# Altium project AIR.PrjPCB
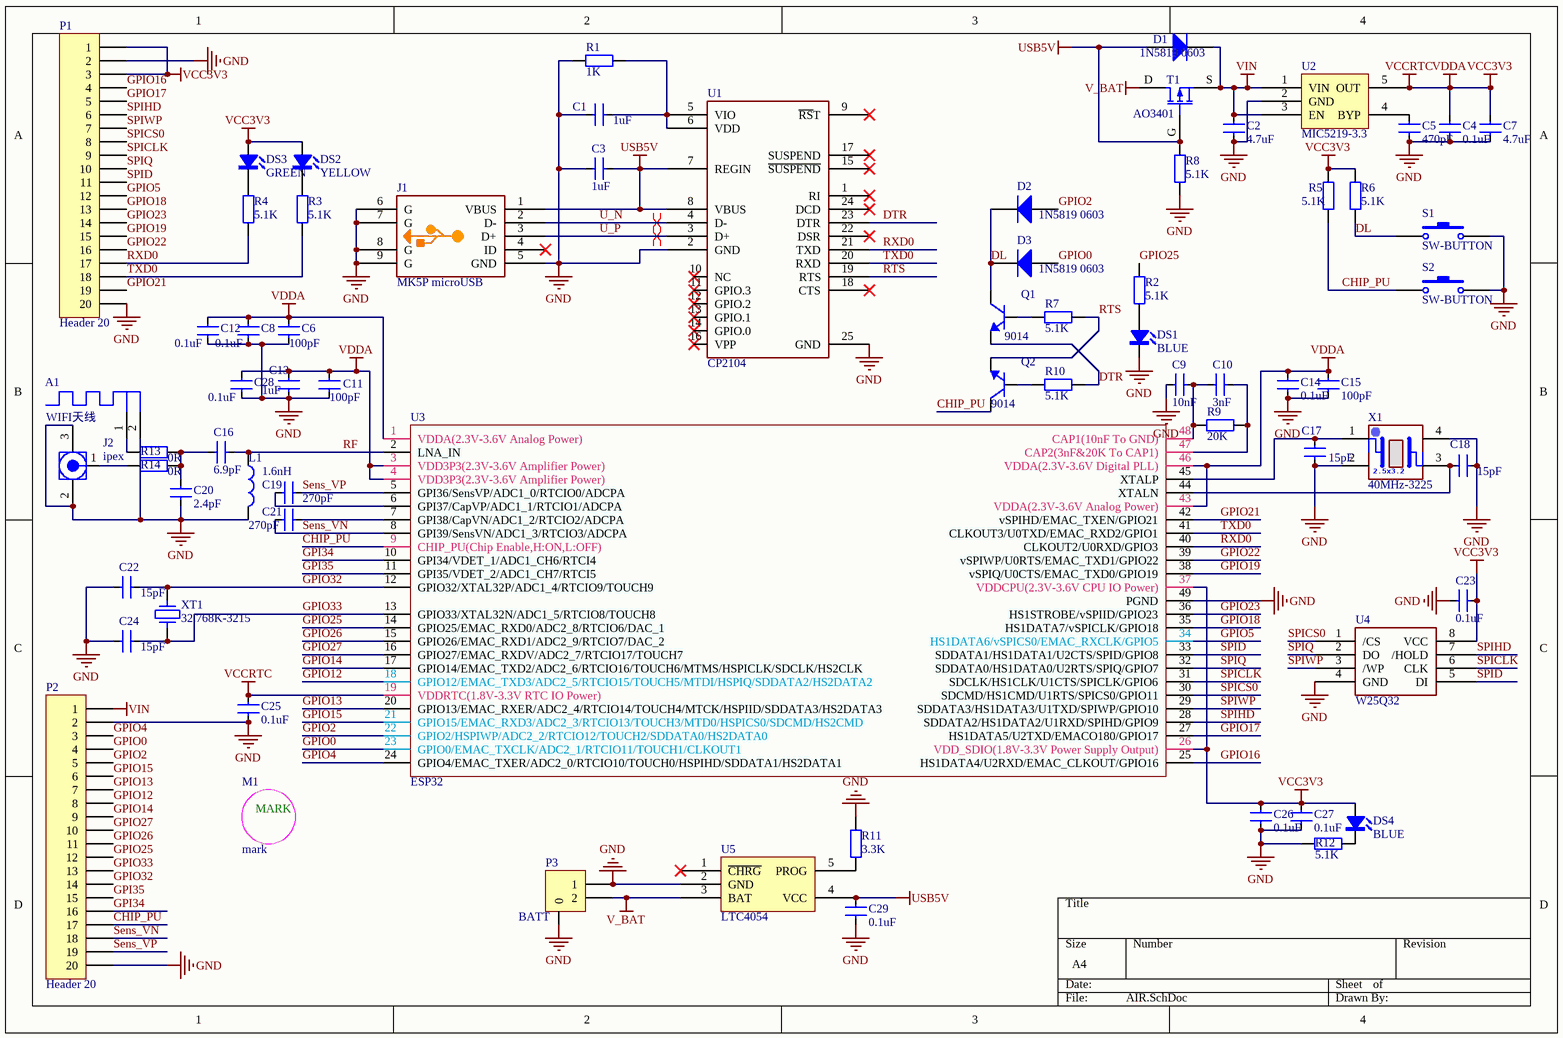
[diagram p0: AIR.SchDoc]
1 sheet, 70 parts. Net scope: global (net labels, ports and power ports of the same name join across sheets).
Board file: AIR.PcbDoc

## Sheet AIR.SchDoc
size A4

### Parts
A1  WIFI天线  [2.4G]
C1  1uF  [C0402]
C2  4.7uF  [C0603]
C3  1uF  [C0402]
C4  0.1uF  [C0402]
C5  470pF  [C0402]
C6  100pF  [C0402]
C7  4.7uF  [C0603]
C8  0.1uF  [C0402]
C9  10nF  [C0402]
C10  3nF  [C0402]
C11  100pF  [C0402]
C12  0.1uF  [C0402]
C13  1uF  [C0402]
C14  0.1uF  [C0402]
C15  100pF  [C0402]
C16  6.9pF  [C0402]
C17  15pF  [C0402]
C18  15pF  [C0402]
C19  270pF  [C0402]
C20  2.4pF  [C0402]
C21  270pF  [C0402]
C22  15pF  [C0402]
C23  0.1uF  [C0402]
C24  15pF  [C0402]
C25  0.1uF  [C0402]
C26  0.1uF  [C0402]
C27  0.1uF  [C0402]
C28  0.1uF  [C0402]
C29  0.1uF  [C0402]
D1  1N5819 0603  [SOD523]
D2  1N5819 0603  [SOD523]
D3  1N5819 0603  [SOD523]
DS1  BLUE  [LED0402]
DS2  YELLOW  [LED0402]
DS3  GREEN  [LED0402]
DS4  BLUE  [LED0402]
J1  MK5P microUSB  [MICROUSB]
J2  ipex  [I-PEX SOCKET]
L1  1.6nH  [L0402]
M1  mark  [ZY_UR-3X2]
P1  Header 20  [HDR1X20-M]
P2  Header 20  [HDR1X20-M]
P3  BATT  [PH1.25-T]
Q1  9014  [SOT23]
Q2  9014  [SOT23]
R1  1K  [R0402]
R2  5.1K  [R0402]
R3  5.1K  [R0402]
R4  5.1K  [R0402]
R5  5.1K  [R0402]
R6  5.1K  [R0402]
R7  5.1K  [R0402]
R8  5.1K  [R0402]
R9  20K  [R0402]
R10  5.1K  [R0402]
R11  3.3K  [R0402]
R12  5.1K  [R0402]
R13  0R  [R0402]
R14  0R  [R0402]
S1  SW-BUTTON  [MINIBUTTON]
S2  SW-BUTTON  [MINIBUTTON]
T1  AO3401  [SOT23]
U1  CP2104  [QFN24]
U2  MIC5219-3.3  [SOT23-5]
U3  ESP32  [QFN40P600X600X100-48N]
U4  W25Q32  [WSON-SPIFLASH]
U5  LTC4054  [SOT23-5]
X1  40MHz-3225  [XTAL3225]
XT1  32.768K-3215  [Y3215]

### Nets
GND: A1.2(G) C1.2 C2.1 C3.1 C4.1 C5.2 C6.1 C7.1 C8.1 C9.2 C11.1 C12.1 C13.1 C14.1 C15.1 C17.2 C18.2 C20.1 C22.1 C23.2 C24.1 C25.1 C26.1 C27.1 C28.1 C29.1 DS1.K J1.5(GND) J1.6(G) J1.7(G) J1.8(G) J1.9(G) J2.2(GND) J2.3(GND) L1.1 P1.2 P1.20 P2.2 P2.20 P3.0 P3.1 R1.1 R8.1 R11.2 R12.2 S1.2 S2.2 U1.2(GND) U1.25(GND) U2.2(GND) U3.49(PGND) U4.4(GND) U5.2(GND) X1.2(NC1) X1.4(NC2)
USB5V: C3.2 C29.2 D1.A J1.1(VBUS) R8.2 T1.G U1.7(REGIN) U1.8(VBUS) U5.4(VCC)
V_BAT: P3.2 T1.D U5.3(BAT)
VCC3V3: C4.2 C6.2 C7.2 C8.2 C11.2 C12.2 C13.2 C14.2 C15.2 C23.1 C25.2 C26.2 C27.2 C28.2 DS2.A DS3.A DS4.A P1.1 P1.3 R5.1 R6.2 U2.5(OUT) U3.1(VDDA(2.3V-3.6V_Analog_Power)) U3.3(VDD3P3(2.3V-3.6V_Amplifier_Power)) U3.4(VDD3P3(2.3V-3.6V_Amplifier_Power)) U3.19(VDDRTC(1.8V-3.3V_RTC_IO_Power)) U3.26(VDD_SDIO(1.8V-3.3V_Power_Supply_Output)) U3.37(VDDCPU(2.3V-3.6V_CPU_IO_Power)) U3.43(VDDA(2.3V-3.6V_Analog_Power)) U3.46(VDDA(2.3V-3.6V_Digital_PLL)) U4.8(VCC)  [also labelled VCCRTC, VDDA]
VIN: C2.2 D1.K P2.1 T1.S U2.1(VIN) U2.3(EN)
CHIP_PU: P2.17 Q2.C R5.2 S2.1 U3.9(CHIP_PU(Chip_Enable,H:ON,L:OFF))
DL: D2.K D3.K Q1.C R6.1 S1.1
DTR: Q1.E R10.1 U1.23(DTR)
GPI34: P2.16 U3.10(GPI34/VDET_1/ADC1_CH6/RTCI4)
GPI35: P2.15 U3.11(GPI35/VDET_2/ADC1_CH7/RTCI5)
GPIO0: D3.A P2.4 U3.23(GPIO0/EMAC_TXCLK/ADC2_1/RTCIO11/TOUCH1/CLKOUT1)
GPIO2: D2.A P2.5 U3.22(GPIO2/HSPIWP/ADC2_2/RTCIO12/TOUCH2/SDDATA0/HS2DATA0)
GPIO4: P2.3 U3.24(GPIO4/EMAC_TXER/ADC2_0/RTCIO10/TOUCH0/HSPIHD/SDDATA1/HS2DATA1)
GPIO5: P1.12 U3.34(HS1DATA6/vSPICS0/EMAC_RXCLK/GPIO5)
GPIO12: P2.8 U3.18(GPIO12/EMAC_TXD3/ADC2_5/RTCIO15/TOUCH5/MTDI/HSPIQ/SDDATA2/HS2DATA2)
GPIO13: P2.7 U3.20(GPIO13/EMAC_RXER/ADC2_4/RTCIO14/TOUCH4/MTCK/HSPIID/SDDATA3/HS2DATA3)
GPIO14: P2.9 U3.17(GPIO14/EMAC_TXD2/ADC2_6/RTCIO16/TOUCH6/MTMS/HSPICLK/SDCLK/HS2CLK)
GPIO15: P2.6 U3.21(GPIO15/EMAC_RXD3/ADC2_3/RTCIO13/TOUCH3/MTD0/HSPICS0/SDCMD/HS2CMD)
GPIO16: P1.4 U3.25(HS1DATA4/U2RXD/EMAC_CLKOUT/GPIO16)
GPIO17: P1.5 U3.27(HS1DATA5/U2TXD/EMACO180/GPIO17)
GPIO18: P1.13 U3.35(HS1DATA7/vSPICLK/GPIO18)
GPIO19: P1.15 U3.38(vSPIQ/U0CTS/EMAC_TXD0/GPIO19)
GPIO21: P1.19 U3.42(vSPIHD/EMAC_TXEN/GPIO21)
GPIO22: P1.16 U3.39(vSPIWP/U0RTS/EMAC_TXD1/GPIO22)
GPIO23: P1.14 U3.36(HS1STROBE/vSPIID/GPIO23)
GPIO25: P2.12 R2.2 U3.14(GPIO25/EMAC_RXD0/ADC2_8/RTCIO6/DAC_1)
GPIO26: P2.11 U3.15(GPIO26/EMAC_RXD1/ADC2_9/RTCIO7/DAC_2)
GPIO27: P2.10 U3.16(GPIO27/EMAC_RXDV/ADC2_7/RTCIO17/TOUCH7)
GPIO32: C22.2 P2.14 U3.12(GPIO32/XTAL32P/ADC1_4/RTCIO9/TOUCH9) XT1.2
GPIO33: C24.2 P2.13 U3.13(GPIO33/XTAL32N/ADC1_5/RTCIO8/TOUCH8) XT1.1
RF: C16.2 L1.2 U3.2(LNA_IN)
RTS: Q2.E R7.1 U1.19(RTS)
RXD0: P1.17 R4.1 U1.21(TXD) U3.40(CLKOUT2/U0RXD/GPIO3)
Sens_VN: C21.1 P2.18 U3.8(GPI39/SensVN/ADC1_3/RTCIO3/ADCPA)
Sens_VP: C19.2 P2.19 U3.5(GPI36/SensVP/ADC1_0/RTCIO0/ADCPA)
SPICLK: P1.9 U3.31(SDCLK/HS1CLK/U1CTS/SPICLK/GPIO6) U4.6(CLK)
SPICS0: P1.8 U3.30(SDCMD/HS1CMD/U1RTS/SPICS0/GPIO11) U4.1(/CS)
SPID: P1.11 U3.33(SDDATA1/HS1DATA1/U2CTS/SPID/GPIO8) U4.5(DI)
SPIHD: P1.6 U3.28(SDDATA2/HS1DATA2/U1RXD/SPIHD/GPIO9) U4.7(/HOLD)
SPIQ: P1.10 U3.32(SDDATA0/HS1DATA0/U2RTS/SPIQ/GPIO7) U4.2(DO)
SPIWP: P1.7 U3.29(SDDATA3/HS1DATA3/U1TXD/SPIWP/GPIO10) U4.3(/WP)
TXD0: P1.18 R3.1 U1.20(RXD) U3.41(CLKOUT3/U0TXD/EMAC_RXD2/GPIO1)
U_N: J1.2(D-) U1.4(D-)
U_P: J1.3(D+) U1.3(D+)
NetA1_1: A1.1 R13.2
NetC1_1: C1.1 R1.2 U1.5(VIO) U1.6(VDD)
NetC5_1: C5.1 U2.4(BYP)
NetC9_1: C9.1 C10.2 R9.2 U3.48(CAP1(10nF_To_GND))
NetC10_1: C10.1 R9.1 U3.47(CAP2(3nF&20K_To_CAP1))
NetC16_1: C16.1 C20.2 R13.1 R14.1
NetC17_1: C17.1 U3.45(XTALP) X1.1(X1)
NetC18_1: C18.1 U3.44(XTALN) X1.3(X2)
NetC19_1: C19.1 U3.6(GPI37/CapVP/ADC1_1/RTCIO1/ADCPA)
NetC21_2: C21.2 U3.7(GPI38/CapVN/ADC1_2/RTCIO2/ADCPA)
NetDS1_A: DS1.A R2.1
NetDS2_K: DS2.K R3.2
NetDS3_K: DS3.K R4.2
NetDS4_K: DS4.K R12.1
NetJ2_1: J2.1(Signal) R14.2
NetQ1_B: Q1.B R7.2
NetQ2_B: Q2.B R10.2
NetR11_1: R11.1 U5.5(PROG)

Not connected (* = marked no-connect by the designer): J1 4(ID)*; U1 1(RI)* 9(~{RS}T)* 10(NC)* 11(GPIO.3)* 12(GPIO.2)* 13(GPIO.1)* 14(GPIO.0)* 15(~{SUSPEND})* 16(VPP)* 17(SUSPEND)* 18(CTS)* 22(DSR)* 24(DCD)*; U5 1(~{CHRG})*

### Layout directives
differential pair: U_N, U_P

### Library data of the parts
A1 = ANT2.4G
C1-C15 C17-C19 C21-C29 = CAP: 普通小电容
C16 C20 = CAP: 射频电容
D1-D3 = Diode: 普通二极管
DS1-DS4 = LED
J1 = MICRO_USB: 4固定脚microUSB座
J2 = MCX_IPEX
L1 = L0402: 射频电感
P1 P2 = Header 20: Header, 20-Pin
P3 = Header 2T: Header, 4-Pin
Q1 Q2 = NPN: NPN三极管; pin to pad: B>1 C>3 E>2
R1-R14 = RES: 普通电阻
T1 = MOS-P: pin to pad: D>3 G>1 S>2
U2 = MIC5219
U4 = SPIFLASH_SOP8W
U5 = LTC4054: 锂电池管理芯片
X1 = XTAL3225
XT1 = XT: 晶振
